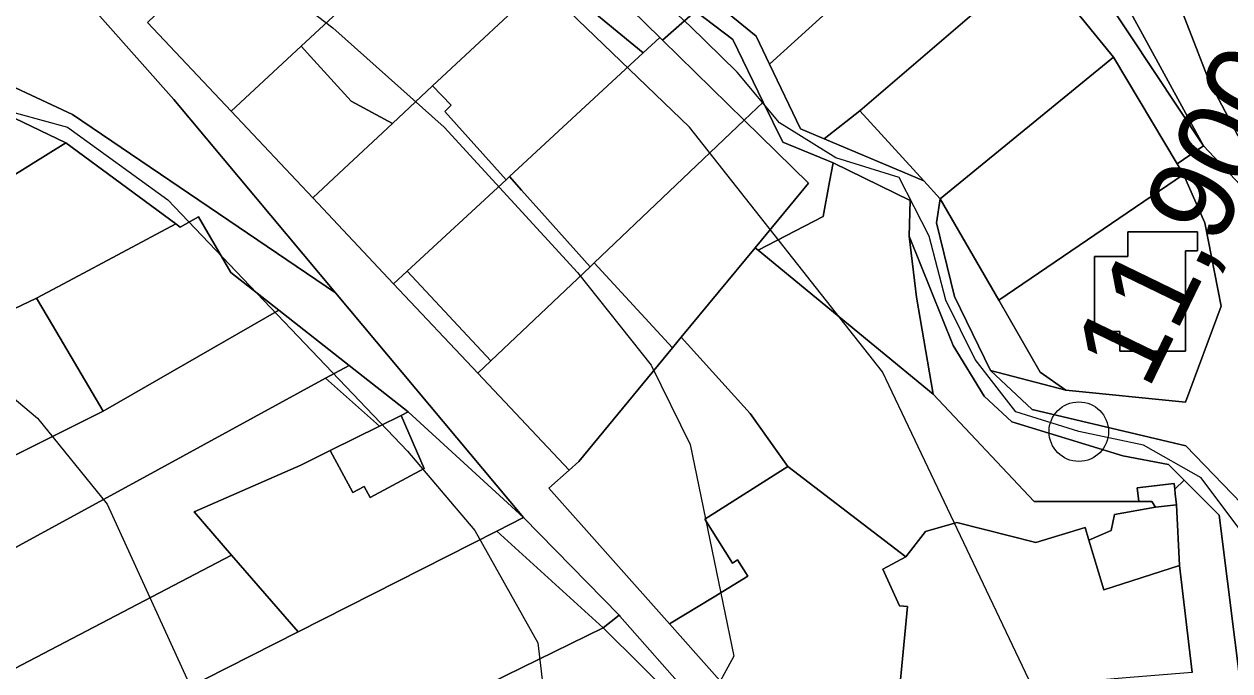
# Model space of a CAD drawing. Extents: x -510989 to -501240, y -1184665 to -1176098.
# Drawn here: x -509745.5 to -509563.3, y -1179013.2 to -1178915.4 of the extents above; entities that cross this region are included whole.
import ezdxf

# ---------------------------------------------------------------- set-up
doc = ezdxf.new("R2010")
doc.units = 0
for name, color, linetype in [('orna_puda', 7, 'Continuous'), ('ostatni_plocha_x_jina_plocha', 7, 'Continuous'), ('ostatni_plocha_x_manipulacni_plocha', 7, 'Continuous'), ('ostatni_plocha_x_neplodna_puda', 7, 'Continuous'), ('ostatni_plocha_x_ostatni_komunikace', 7, 'Continuous'), ('ovocny_sad', 7, 'Continuous'), ('trasovani_toku', 7, 'Continuous'), ('trvaly_travni_porost', 7, 'Continuous'), ('vodni_plocha_x_vodni_tok_v_koryte_umelem', 7, 'Continuous'), ('vrstevnice_01', 7, 'Continuous'), ('vrstevnice_02', 7, 'Continuous'), ('zahrada', 7, 'Continuous'), ('zastavena_plocha_a_nadvori', 7, 'Continuous')]:
    doc.layers.add(name, color=color, linetype=linetype)

msp = doc.modelspace()

# ---------------------------------------------------------------- linework, layer by layer
at = {"layer": 'orna_puda'}
for points in [[(-509747.01, -1178929.64), (-509739.25, -1178933.41), (-509750.37, -1178940.29), (-509826.41, -1178972.46), (-509865.26, -1178988.73), (-509896.7, -1179000.67), (-509905.97, -1178992.88)], [(-509739.25, -1178933.41), (-509722.64, -1178945.64), (-509738.82, -1178954.28), (-509743.69, -1178956.88), (-509782.48, -1178975.39), (-509831.95, -1178996.1), (-509867.28, -1179012.99), (-509895.53, -1179001.65), (-509896.7, -1179000.67), (-509865.26, -1178988.73), (-509826.41, -1178972.46), (-509750.37, -1178940.29)], [(-509696.44, -1178967.05), (-509699.99, -1178968.99), (-509725.35, -1178982.83), (-509829.61, -1179039.72), (-509832.41, -1179036.78), (-509844.16, -1179029.3), (-509733.59, -1178973.95), (-509733.23, -1178973.74), (-509707.07, -1178958.69)], [(-509699.99, -1178968.99), (-509691.83, -1178976.2), (-509699.28, -1178979.89), (-509703.75, -1178982.11), (-509719.85, -1178989.18), (-509714.2, -1178995.7), (-509819.24, -1179050.63), (-509829.61, -1179039.72), (-509725.35, -1178982.83)], [(-509658.04, -1179006.71), (-509680.26, -1179017.61), (-509690.74, -1179022.76), (-509720.9, -1179037.56), (-509753.19, -1179053.67), (-509754.54, -1179050.86), (-509771.37, -1179058.96), (-509799.91, -1179072.7), (-509806.86, -1179065.84), (-509810.58, -1179061.28), (-509704.14, -1179007.3), (-509674.13, -1178992.08)], [(-509714.2, -1178995.7), (-509704.14, -1179007.3), (-509810.58, -1179061.28), (-509819.24, -1179050.63)]]:
    msp.add_lwpolyline(points, close=True, dxfattribs=at)
at = {"layer": 'ostatni_plocha_x_jina_plocha'}
for points in [[(-509592.83, -1178905.8), (-509580.92, -1178920.45), (-509607.12, -1178941.83), (-509609.6, -1178939.11), (-509619.24, -1178928.53)], [(-509580.92, -1178920.45), (-509571.29, -1178936.57), (-509570.33, -1178938.18), (-509598.27, -1178957.17), (-509607.12, -1178941.83)]]:
    msp.add_lwpolyline(points, close=True, dxfattribs=at)
at = {"layer": 'ostatni_plocha_x_manipulacni_plocha'}
for points in [[(-509570.33, -1178938.18), (-509567.13, -1178945.5), (-509564.65, -1178958.06), (-509570.04, -1178972.58), (-509588.1, -1178970.78), (-509591.98, -1178968.07), (-509598.27, -1178957.17)], [(-509578.73, -1178946.86), (-509578.73, -1178950.55), (-509583.78, -1178950.55), (-509583.78, -1178961.89), (-509579.96, -1178961.89), (-509579.96, -1178964.9), (-509570.05, -1178964.9), (-509570.05, -1178952.12), (-509570.05, -1178949.72), (-509568.24, -1178949.72), (-509568.24, -1178946.86)], [(-509699.99, -1178968.99), (-509696.44, -1178967.05), (-509687.52, -1178974.06), (-509688.59, -1178974.59), (-509691.83, -1178976.2)], [(-509674.13, -1178992.08), (-509670.08, -1178990.03), (-509655.63, -1179004.82), (-509658.04, -1179006.71)], [(-509655.53, -1179004.93), (-509644.59, -1179017.35), (-509646.58, -1179018.07), (-509658.04, -1179006.71), (-509655.63, -1179004.82)]]:
    msp.add_lwpolyline(points, close=True, dxfattribs=at)
at = {"layer": 'ostatni_plocha_x_neplodna_puda'}
for points in [[(-509784.86, -1178853.38), (-509787.09, -1178843.21), (-509744.08, -1178902.94), (-509722.94, -1178926.83), (-509698.48, -1178956.07), (-509738.24, -1178929.11), (-509776.5, -1178911.17), (-509796.44, -1178910.41), (-509801.38, -1178910.9), (-509796.15, -1178904.65), (-509777.03, -1178902), (-509756.82, -1178908.97), (-509752.09, -1178907.45), (-509752.59, -1178906.62), (-509746.83, -1178903.09), (-509762.32, -1178882.67), (-509771.17, -1178871.84), (-509790.99, -1178875.6), (-509788.07, -1178872.9), (-509784.07, -1178861.1)], [(-509695.13, -1178872.62), (-509689.36, -1178872.62), (-509685.15, -1178878.25), (-509664.01, -1178878.13), (-509655.75, -1178906.31), (-509649.2, -1178909.59), (-509644.09, -1178913.48), (-509649.06, -1178917.86), (-509649.47, -1178917.46), (-509662.4, -1178904.75), (-509675.09, -1178892.3), (-509688.86, -1178878.77)], [(-509644.09, -1178913.48), (-509638.43, -1178917.79), (-509633.84, -1178927.26), (-509636.71, -1178929.98), (-509649.06, -1178917.86)], [(-509689.72, -1178954.7), (-509687.66, -1178952.8), (-509675, -1178966.35), (-509676.98, -1178968.23)]]:
    msp.add_lwpolyline(points, close=True, dxfattribs=at)
at = {"layer": 'ostatni_plocha_x_ostatni_komunikace'}
for points in [[(-509604.46, -1178865.81), (-509567.3, -1178933.86), (-509582.32, -1178911.15)], [(-509726.88, -1178915.18), (-509714.27, -1178928.59), (-509701.93, -1178941.71), (-509689.72, -1178954.7), (-509676.98, -1178968.23), (-509663.2, -1178982.89), (-509666.24, -1178985.59), (-509647.99, -1179006.13), (-509635.21, -1179020.52), (-509634.67, -1179021.12), (-509635.46, -1179022.46), (-509635.52, -1179027.88), (-509639.96, -1179022.71), (-509643.82, -1179018.22), (-509643.89, -1179018.15), (-509644.59, -1179017.35), (-509655.53, -1179004.93), (-509655.63, -1179004.82), (-509670.08, -1178990.03), (-509698.48, -1178956.07), (-509722.94, -1178926.83), (-509744.08, -1178902.94)], [(-509582.32, -1178911.15), (-509567.3, -1178933.86), (-509571.29, -1178936.57), (-509580.92, -1178920.45), (-509592.83, -1178905.8)], [(-509776.5, -1178911.17), (-509738.24, -1178929.11), (-509698.48, -1178956.07), (-509670.08, -1178990.03), (-509687.52, -1178974.06), (-509696.44, -1178967.05), (-509707.07, -1178958.69), (-509714.31, -1178952.99), (-509719.19, -1178944.56), (-509721.94, -1178946.15), (-509722.64, -1178945.64), (-509739.25, -1178933.41), (-509747.01, -1178929.64), (-509754.51, -1178925.99), (-509774.05, -1178916.48), (-509779.07, -1178914.04)], [(-509561.55, -1178987.93), (-509570.01, -1178979.19), (-509593.22, -1178973.69), (-509599.53, -1178967.8), (-509588.1, -1178970.78), (-509570.04, -1178972.58), (-509564.65, -1178958.06), (-509567.13, -1178945.5), (-509570.33, -1178938.18), (-509571.29, -1178936.57), (-509567.3, -1178933.86), (-509555.31, -1178946.59)], [(-509569.04, -1179013.45), (-509570.93, -1178997.28), (-509571.4, -1178988.1), (-509571.59, -1178986.43), (-509571.67, -1178985.73), (-509570.25, -1178984.4), (-509564.96, -1178989.69), (-509559.03, -1179036.98)]]:
    msp.add_lwpolyline(points, dxfattribs=at)
msp.add_lwpolyline([(-509633.84, -1178927.26), (-509630.91, -1178933.3), (-509623.29, -1178936.39), (-509623.82, -1178939.29), (-509624.78, -1178944.51), (-509634.61, -1178949.63), (-509635.06, -1178949.26), (-509628.15, -1178940.89), (-509627.01, -1178939.51), (-509636.71, -1178929.98)], close=True, dxfattribs=at)
at = {"layer": 'ovocny_sad'}
msp.add_lwpolyline([(-509743.69, -1178956.88), (-509741.27, -1178960.96), (-509733.59, -1178973.95), (-509844.16, -1179029.3), (-509844.59, -1179029.03), (-509867.28, -1179012.99), (-509831.95, -1178996.1), (-509782.48, -1178975.39)], close=True, dxfattribs=at)
at = {"layer": 'trasovani_toku'}
for p, q in [((-509644.94, -1178915.72), (-509652.29, -1178908.94)), ((-509637.78, -1178922.7), (-509644.94, -1178915.72)), ((-509631.38, -1178930.39), (-509637.78, -1178922.7)), ((-509622.87, -1178935.64), (-509631.38, -1178930.39)), ((-509613.33, -1178938.62), (-509622.87, -1178935.64)), ((-509608.75, -1178947.51), (-509613.33, -1178938.62)), ((-509606.27, -1178957.19), (-509608.75, -1178947.51)), ((-509601.83, -1178966.16), (-509606.27, -1178957.19)), ((-509595.7, -1178974.06), (-509601.83, -1178966.16)), ((-509586.16, -1178977.05), (-509595.7, -1178974.06)), ((-509576.37, -1178979.1), (-509586.16, -1178977.05)), ((-509567.66, -1178984.02), (-509576.37, -1178979.1)), ((-509561.69, -1178992.04), (-509567.66, -1178984.02))]:
    msp.add_line(p, q, dxfattribs=at)
msp.add_circle((-509586.16, -1178977.05), 4.5, dxfattribs=at)
at = {"layer": 'trvaly_travni_porost'}
msp.add_lwpolyline([(-509562.14, -1178932.28), (-509566.44, -1178924.06), (-509569.79, -1178915.5), (-509576.71, -1178897.88), (-509584.84, -1178883.94), (-509605.41, -1178859.83), (-509608.22, -1178841.97), (-509618.72, -1178802.31), (-509628.57, -1178783.46), (-509635.85, -1178778.43), (-509580.92, -1178737.68), (-509547.35, -1178710.26)], dxfattribs=at)
for points in [[(-509604.46, -1178865.81), (-509605.41, -1178859.83), (-509584.84, -1178883.94), (-509576.71, -1178897.88), (-509569.79, -1178915.5), (-509566.44, -1178924.06), (-509562.14, -1178932.28), (-509555.85, -1178941.14), (-509554.87, -1178946.25), (-509555.31, -1178946.59), (-509567.3, -1178933.86)], [(-509623.29, -1178936.39), (-509611.67, -1178942.11), (-509611.82, -1178947.5), (-509610.69, -1178956.72), (-509608.16, -1178971.4), (-509634.61, -1178949.63), (-509624.78, -1178944.51), (-509623.82, -1178939.29)], [(-509611.82, -1178947.5), (-509605.13, -1178964.01), (-509600.45, -1178971.67), (-509596.26, -1178975.59), (-509579.53, -1178980.7), (-509572.63, -1178982.01), (-509570.25, -1178984.4), (-509571.67, -1178985.73), (-509571.77, -1178984.91), (-509577.35, -1178985.57), (-509577.11, -1178987.62), (-509592.93, -1178987.62), (-509608.16, -1178971.4), (-509610.69, -1178956.72)]]:
    msp.add_lwpolyline(points, close=True, dxfattribs=at)
at = {"layer": 'vodni_plocha_x_vodni_tok_v_koryte_umelem'}
for points in [[(-509643.34, -1178910.36), (-509634.91, -1178917.24), (-509632.89, -1178921.5), (-509628.24, -1178931.28), (-509624.62, -1178932.8), (-509609.6, -1178939.11), (-509607.12, -1178941.83), (-509607.68, -1178945.49), (-509604.96, -1178956.6), (-509599.53, -1178967.8), (-509593.22, -1178973.69), (-509570.01, -1178979.19), (-509561.55, -1178987.93)], [(-509559.03, -1179036.98), (-509564.96, -1178989.69), (-509570.25, -1178984.4), (-509572.63, -1178982.01), (-509579.53, -1178980.7), (-509596.26, -1178975.59), (-509600.45, -1178971.67), (-509605.13, -1178964.01), (-509611.82, -1178947.5), (-509611.67, -1178942.11), (-509623.29, -1178936.39), (-509630.91, -1178933.3), (-509633.84, -1178927.26), (-509638.43, -1178917.79), (-509644.09, -1178913.48)]]:
    msp.add_lwpolyline(points, dxfattribs=at)
at = {"layer": 'vrstevnice_01'}
for points in [[(-509859.5, -1178892), (-509851.81, -1178924), (-509844.5, -1178939), (-509831.41, -1178953), (-509818.59, -1178961), (-509801.5, -1178963), (-509762.81, -1178963), (-509753.09, -1178967), (-509743.5, -1178975), (-509733, -1178988), (-509717.5, -1179022), (-509713.09, -1179040), (-509712.81, -1179053), (-509714.91, -1179060), (-509701.69, -1179094), (-509700.09, -1179103), (-509699.91, -1179126), (-509704.19, -1179151)], [(-509710.69, -1178907), (-509698.91, -1178916), (-509682.09, -1178931), (-509661.91, -1178953), (-509650.81, -1178967), (-509644.91, -1178979), (-509638.31, -1179011), (-509644.31, -1179022), (-509643.09, -1179035), (-509640.31, -1179041), (-509629.41, -1179051), (-509623, -1179059), (-509616.59, -1179074), (-509613.19, -1179088), (-509611.09, -1179125), (-509613.91, -1179157)]]:
    msp.add_lwpolyline(points, dxfattribs=at)
at = {"layer": 'vrstevnice_02'}
for points in [[(-509589.31, -1179170), (-509587.69, -1179130), (-509589.69, -1179112), (-509590, -1179091), (-509586.5, -1179079), (-509580.91, -1179066), (-509582.81, -1179046), (-509587.31, -1179028), (-509615.81, -1178968), (-509645, -1178931), (-509676.19, -1178901)], [(-509798.59, -1178913), (-509792.5, -1178922), (-509787.69, -1178924), (-509757.41, -1178926), (-509739, -1178931), (-509723.81, -1178942), (-509687.59, -1178980), (-509677.41, -1178992), (-509667.91, -1179009), (-509665.81, -1179027), (-509665.69, -1179039), (-509657.81, -1179084), (-509656.31, -1179113), (-509666.59, -1179164)]]:
    msp.add_lwpolyline(points, dxfattribs=at)
at = {"layer": 'zahrada'}
for points in [[(-509675.09, -1178892.3), (-509662.4, -1178904.75), (-509666.06, -1178908.17), (-509683.81, -1178924.77), (-509689.9, -1178930.46), (-509696.13, -1178927.07), (-509702.27, -1178920.33), (-509703.68, -1178918.78), (-509698.19, -1178913.69)], [(-509608.08, -1178898.93), (-509603.59, -1178900.97), (-509594.49, -1178903.76), (-509592.83, -1178905.8), (-509619.24, -1178928.53), (-509624.62, -1178932.8), (-509628.24, -1178931.28), (-509632.89, -1178921.5)], [(-509662.4, -1178904.75), (-509649.47, -1178917.46), (-509651.98, -1178919.78), (-509666.06, -1178908.17)], [(-509666.06, -1178908.17), (-509651.98, -1178919.78), (-509672.2, -1178938.49), (-509672.71, -1178938.96), (-509681.99, -1178928.64), (-509681, -1178927.68), (-509683.81, -1178924.77)], [(-509649.47, -1178917.46), (-509649.06, -1178917.86), (-509636.71, -1178929.98), (-509659.38, -1178951.51), (-509660.02, -1178952.12), (-509667.32, -1178943.95), (-509670.39, -1178940.52), (-509672.2, -1178938.49), (-509651.98, -1178919.78)], [(-509619.24, -1178928.53), (-509609.6, -1178939.11), (-509624.62, -1178932.8)], [(-509636.71, -1178929.98), (-509627.01, -1178939.51), (-509628.15, -1178940.89), (-509635.06, -1178949.26), (-509646.23, -1178962.79), (-509647.55, -1178964.39), (-509659.38, -1178951.51)], [(-509607.68, -1178945.49), (-509607.12, -1178941.83), (-509598.27, -1178957.17), (-509591.98, -1178968.07), (-509588.1, -1178970.78), (-509599.53, -1178967.8), (-509604.96, -1178956.6)], [(-509634.61, -1178949.63), (-509608.16, -1178971.4), (-509592.93, -1178987.62), (-509577.11, -1178987.62), (-509575.12, -1178987.62), (-509574.58, -1178988.47), (-509580.76, -1178989.57), (-509581.27, -1178992.01), (-509584.64, -1178993.46), (-509585.21, -1178991.56), (-509592.65, -1178993.81), (-509604.6, -1178990.79), (-509609.35, -1178992.13), (-509612.28, -1178995.97), (-509630.13, -1178982.34), (-509635.84, -1178974.32), (-509646.23, -1178962.79), (-509635.06, -1178949.26)], [(-509646.23, -1178962.79), (-509635.84, -1178974.32), (-509630.13, -1178982.34), (-509642.69, -1178990.26), (-509638.49, -1178996.92), (-509637.75, -1178996.45), (-509636.2, -1178998.9), (-509641.28, -1179002.02), (-509647.99, -1179006.13), (-509666.24, -1178985.59), (-509663.2, -1178982.89), (-509661.73, -1178981.58), (-509647.55, -1178964.39)], [(-509687.52, -1178974.06), (-509670.08, -1178990.03), (-509674.13, -1178992.08), (-509704.14, -1179007.3), (-509714.2, -1178995.7), (-509719.85, -1178989.18), (-509703.75, -1178982.11), (-509699.28, -1178979.89), (-509695.87, -1178986.23), (-509694.18, -1178985.32), (-509693.27, -1178987.01), (-509685.1, -1178982.62), (-509688.59, -1178974.59)]]:
    msp.add_lwpolyline(points, close=True, dxfattribs=at)
at = {"layer": 'zastavena_plocha_a_nadvori'}
for points in [[(-509637.2, -1178889.66), (-509635.01, -1178890.32), (-509618.7, -1178895.23), (-509611.41, -1178897.42), (-509608.08, -1178898.93), (-509632.89, -1178921.5), (-509634.91, -1178917.24), (-509643.34, -1178910.36)], [(-509709.13, -1178901.11), (-509707.91, -1178899.97), (-509703.3, -1178904.85), (-509704.74, -1178906.2), (-509698.19, -1178913.69), (-509703.68, -1178918.78), (-509714.27, -1178928.59), (-509726.88, -1178915.18), (-509710.51, -1178899.51)], [(-509703.68, -1178918.78), (-509702.27, -1178920.33), (-509696.13, -1178927.07), (-509689.9, -1178930.46), (-509697.96, -1178938), (-509701.93, -1178941.71), (-509714.27, -1178928.59)], [(-509681, -1178927.68), (-509681.99, -1178928.64), (-509672.71, -1178938.96), (-509687.66, -1178952.8), (-509689.72, -1178954.7), (-509701.93, -1178941.71), (-509697.96, -1178938), (-509689.9, -1178930.46), (-509683.81, -1178924.77)], [(-509672.71, -1178938.96), (-509672.2, -1178938.49), (-509670.39, -1178940.52), (-509667.32, -1178943.95), (-509660.02, -1178952.12), (-509675, -1178966.35), (-509687.66, -1178952.8)], [(-509719.19, -1178944.56), (-509714.31, -1178952.99), (-509707.07, -1178958.69), (-509733.23, -1178973.74), (-509733.59, -1178973.95), (-509741.27, -1178960.96), (-509743.69, -1178956.88), (-509738.82, -1178954.28), (-509722.64, -1178945.64), (-509721.94, -1178946.15)], [(-509578.73, -1178946.86), (-509568.24, -1178946.86), (-509568.24, -1178949.72), (-509570.05, -1178949.72), (-509570.05, -1178952.12), (-509570.05, -1178964.9), (-509579.96, -1178964.9), (-509579.96, -1178961.89), (-509583.78, -1178961.89), (-509583.78, -1178950.55), (-509578.73, -1178950.55)], [(-509659.38, -1178951.51), (-509647.55, -1178964.39), (-509661.73, -1178981.58), (-509663.2, -1178982.89), (-509676.98, -1178968.23), (-509675, -1178966.35), (-509660.02, -1178952.12)], [(-509688.59, -1178974.59), (-509685.1, -1178982.62), (-509693.27, -1178987.01), (-509694.18, -1178985.32), (-509695.87, -1178986.23), (-509699.28, -1178979.89), (-509691.83, -1178976.2)], [(-509642.69, -1178990.26), (-509630.13, -1178982.34), (-509612.28, -1178995.97), (-509615.78, -1178997.84), (-509613.25, -1179003.38), (-509612.05, -1179003.49), (-509613.01, -1179013.53), (-509613.39, -1179017.55), (-509614.01, -1179017.67), (-509618.85, -1179018.57), (-509623.42, -1179024.16), (-509625.97, -1179019.37), (-509629.03, -1179022.74), (-509632.99, -1179022.1), (-509634.67, -1179021.12), (-509635.21, -1179020.52), (-509647.99, -1179006.13), (-509641.28, -1179002.02), (-509636.2, -1178998.9), (-509637.75, -1178996.45), (-509638.49, -1178996.92)], [(-509571.77, -1178984.91), (-509571.67, -1178985.73), (-509571.59, -1178986.43), (-509571.4, -1178988.1), (-509574.58, -1178988.47), (-509575.12, -1178987.62), (-509577.11, -1178987.62), (-509577.35, -1178985.57)], [(-509574.58, -1178988.47), (-509571.4, -1178988.1), (-509570.93, -1178997.28), (-509582.36, -1179000.96), (-509584.64, -1178993.46), (-509581.27, -1178992.01), (-509580.76, -1178989.57)], [(-509609.35, -1178992.13), (-509604.6, -1178990.79), (-509592.65, -1178993.81), (-509585.21, -1178991.56), (-509584.64, -1178993.46), (-509582.36, -1179000.96), (-509570.93, -1178997.28), (-509569.04, -1179013.45), (-509578.39, -1179014.24), (-509584.38, -1179014.74), (-509592.54, -1179015.43), (-509609.81, -1179016.88), (-509613.39, -1179017.55), (-509613.01, -1179013.53), (-509612.05, -1179003.49), (-509613.25, -1179003.38), (-509615.78, -1178997.84), (-509612.28, -1178995.97)], [(-509680.26, -1179017.61), (-509658.04, -1179006.71), (-509646.58, -1179018.07), (-509675.09, -1179028.39), (-509676.24, -1179026), (-509679.51, -1179019.17)]]:
    msp.add_lwpolyline(points, close=True, dxfattribs=at)

# ---------------------------------------------------------------- texts
at = {"layer": 'trasovani_toku'}
msp.add_text('11,900', height=13, rotation=64.103, dxfattribs=at).set_placement((-509575.7, -1178970.94))

doc.saveas('drawing.dxf')
